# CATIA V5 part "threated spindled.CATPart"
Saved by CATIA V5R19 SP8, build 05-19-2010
Part number: threated spindled
Bounding box of the stored display mesh (mm): x 8 to 136.206, y 123.1 to 137.1, z -21.504 to -7.856
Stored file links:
  G:\EU_thinkMotion\CFAO_2010\MMS_groupe1\MMS_groupe1\A reprendre\gduval\CFAO kinematic ok\threated spindled.CATPart
  G:\EU_thinkMotion\CFAO_2010\MMS_groupe1\MMS_groupe1\A reprendre\gduval\CFAO kinematic ok\worm wheel.CATPart
  C:\Users\guillaume\ecole\Cours IFMA\S3\CFAO\brevet Think motion\CATIA\skeleton worm wheel.CATPart
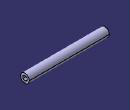
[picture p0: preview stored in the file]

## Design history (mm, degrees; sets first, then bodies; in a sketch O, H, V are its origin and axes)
Body1 (main body)
  Plane1: stored without definition
  Point1: stored without definition
  Point2: stored without definition
  Line1: type PtPt, FirstPoint Point1, SecondPoint Point2
  Plane2: stored without definition
  Plane3: type Normal, Curve Line1, RefPoint Point2
  Sketch1 on Plane1, origin (8, 0, 0), H (0, 1, 0), V (0, 0, 1)
    circle A1 centre (130.1, -14.68) radius 7
    point P1 (130.1, -14.68)
    reference projected point E1 (130.1, -14.68) from Line1
    point P2 (126.6, -12.6593)
    point P3 (126.6, -16.7007)
    point P4 (130.1, -18.7215)
    point P5 (133.6, -16.7007)
    point P6 (133.6, -12.6593)
    point P7 (130.1, -10.6385)
    point P8 (126.6, -14.68)
    line L1 (126.6, -12.6593) -> (126.6, -16.7007)
    line L2 (126.6, -16.7007) -> (130.1, -18.7215)
    line L3 (130.1, -18.7215) -> (133.6, -16.7007)
    line L4 (133.6, -16.7007) -> (133.6, -12.6593)
    line L5 (133.6, -12.6593) -> (130.1, -10.6385)
    line L6 (130.1, -10.6385) -> (126.6, -12.6593)
    construction line L7 (130.1, -14.68) -> (126.6, -14.68)
    construction circle A2 centre (130.1, -14.68) radius 4.0415
    construction arc A3 centre (133.6, -12.6593) radius 4.0415 from (133.6, -16.7007) to (130.1, -10.6385) cw
    construction arc A4 centre (126.6, -16.7007) radius 4.0415 from (130.1, -18.7215) to (126.6, -12.6593) ccw
    radius A1 = 7
    distance L5 L2 = 7
    coincidence: P1 E1, A2 P2, A2 P3, A2 P4, A2 P5, A2 P6, A2 P7, A3 P1, A4 P1
    horizontal: L7 H
    midpoint: P8 L1
    parallelism: L1 L4
  Pad1: profile Sketch1, direction (1, 0, 0), up to Plane3
  Plane4: stored without definition
  Line2: type Normal, RefPoint Point1, RefSkin Plane4, Start -20, End 20
  Thread1: diameter 14, depth 128.206, pitch 2, on face of Pad1 from Sketch1.A1, from end face of Pad1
